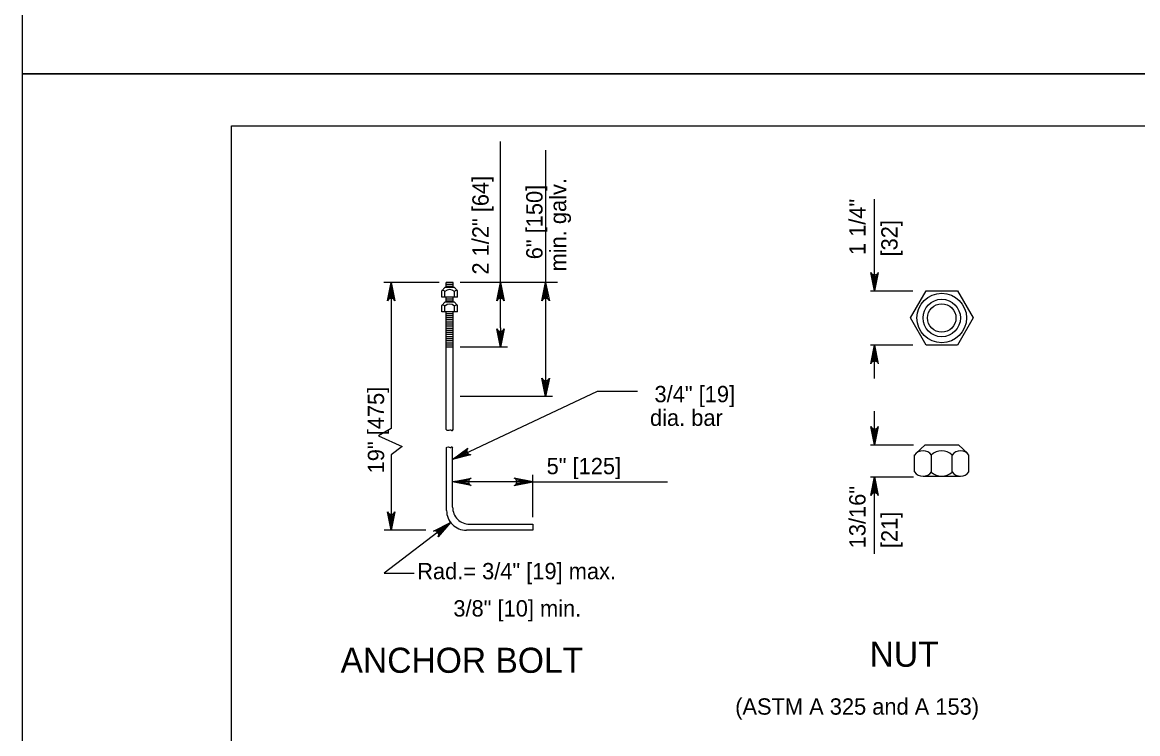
# Model space of a CAD drawing. Extents: x 1083.1 to 1117.1, y 675.4 to 741.4.
# Drawn here: x 1083.13 to 1093.79, y 691.05 to 697.84 of the extents above; entities that cross this region are included whole.
import ezdxf

# ---------------------------------------------------------------- set-up
doc = ezdxf.new("R2010")
doc.units = 0
doc.layers.add('Level 1', color=7, linetype='Continuous')

msp = doc.modelspace()

# ---------------------------------------------------------------- linework, layer by layer
at = {"layer": 'Level 1'}
for p, q in [((1117.126, 697.354), (1083.126, 697.354)), ((1083.126, 697.354), (1083.126, 675.354)), ((1087.696, 694.925), (1087.696, 696.707)), ((1088.127, 696.623), (1088.127, 694.268)), ((1091.272, 695.278), (1091.272, 696.156)), ((1091.249, 695.438), (1091.272, 695.278)), ((1091.26, 695.433), (1091.272, 695.278)), ((1091.296, 695.44), (1091.272, 695.278)), ((1091.286, 695.434), (1091.272, 695.278)), ((1091.272, 695.431), (1091.272, 695.278)), ((1087.109, 695.359), (1086.58, 695.359)), ((1086.628, 695.197), (1086.652, 695.359)), ((1086.638, 695.203), (1086.652, 695.359)), ((1086.652, 695.206), (1086.652, 695.359)), ((1086.664, 695.204), (1086.652, 695.359)), ((1086.675, 695.199), (1086.652, 695.359)), ((1086.652, 695.359), (1086.652, 693.963)), ((1087.135, 695.28), (1087.163, 695.31)), ((1087.257, 695.31), (1087.163, 695.31)), ((1087.176, 695.31), (1087.176, 695.359)), ((1087.245, 695.359), (1087.176, 695.359)), ((1087.245, 695.339), (1087.176, 695.339)), ((1087.245, 695.319), (1087.176, 695.319)), ((1087.245, 695.31), (1087.245, 695.359)), ((1087.285, 695.28), (1087.257, 695.31)), ((1088.24, 695.359), (1087.311, 695.359)), ((1087.671, 695.197), (1087.696, 695.359)), ((1087.682, 695.203), (1087.696, 695.359)), ((1087.696, 695.206), (1087.696, 695.359)), ((1087.708, 695.204), (1087.696, 695.359)), ((1087.719, 695.199), (1087.696, 695.359)), ((1088.102, 695.197), (1088.127, 695.359)), ((1088.113, 695.203), (1088.127, 695.359)), ((1088.127, 695.206), (1088.127, 695.359)), ((1088.139, 695.204), (1088.127, 695.359)), ((1088.15, 695.199), (1088.127, 695.359)), ((1087.135, 695.219), (1087.135, 695.28)), ((1087.285, 695.219), (1087.135, 695.219)), ((1087.164, 695.219), (1087.164, 695.273)), ((1087.176, 695.17), (1087.176, 695.219)), ((1087.245, 695.2), (1087.176, 695.2)), ((1087.245, 695.17), (1087.245, 695.219)), ((1087.256, 695.219), (1087.256, 695.273)), ((1087.285, 695.219), (1087.285, 695.28)), ((1091.232, 695.278), (1091.636, 695.278)), ((1091.613, 695.019), (1091.763, 695.278)), ((1091.763, 695.278), (1092.063, 695.278)), ((1092.063, 695.278), (1092.213, 695.019)), ((1087.135, 695.14), (1087.163, 695.17)), ((1087.135, 695.079), (1087.135, 695.14)), ((1087.257, 695.17), (1087.163, 695.17)), ((1087.164, 695.079), (1087.164, 695.133)), ((1087.245, 695.18), (1087.176, 695.18)), ((1087.256, 695.079), (1087.256, 695.133)), ((1087.285, 695.14), (1087.257, 695.17)), ((1087.285, 695.079), (1087.285, 695.14)), ((1087.285, 695.079), (1087.135, 695.079)), ((1087.244, 695.079), (1087.175, 695.079)), ((1087.176, 693.954), (1087.176, 695.079)), ((1087.245, 695.06), (1087.176, 695.06)), ((1087.245, 695.04), (1087.176, 695.04)), ((1087.245, 695.02), (1087.176, 695.02)), ((1087.245, 695), (1087.176, 695)), ((1087.245, 693.954), (1087.245, 695.079)), ((1091.763, 694.759), (1091.613, 695.019)), ((1092.213, 695.019), (1092.063, 694.759)), ((1087.245, 694.98), (1087.176, 694.98)), ((1087.245, 694.96), (1087.176, 694.96)), ((1087.245, 694.94), (1087.176, 694.94)), ((1087.245, 694.92), (1087.176, 694.92)), ((1087.245, 694.9), (1087.176, 694.9)), ((1087.245, 694.88), (1087.176, 694.88)), ((1087.674, 694.9), (1087.696, 694.74)), ((1087.685, 694.895), (1087.696, 694.74)), ((1087.696, 694.925), (1087.696, 694.74)), ((1087.721, 694.902), (1087.696, 694.74)), ((1087.711, 694.896), (1087.696, 694.74)), ((1087.696, 694.893), (1087.696, 694.74)), ((1087.245, 694.86), (1087.176, 694.86)), ((1087.245, 694.84), (1087.176, 694.84)), ((1087.245, 694.82), (1087.176, 694.82)), ((1087.245, 694.8), (1087.176, 694.8)), ((1087.245, 694.78), (1087.176, 694.78)), ((1087.245, 694.76), (1087.176, 694.76)), ((1087.245, 694.74), (1087.176, 694.74)), ((1087.763, 694.74), (1087.311, 694.74)), ((1091.636, 694.759), (1091.232, 694.759)), ((1091.247, 694.597), (1091.272, 694.759)), ((1091.257, 694.603), (1091.272, 694.759)), ((1091.272, 694.441), (1091.272, 694.759)), ((1091.272, 694.606), (1091.272, 694.759)), ((1091.283, 694.604), (1091.272, 694.759)), ((1091.294, 694.599), (1091.272, 694.759)), ((1092.063, 694.759), (1091.763, 694.759)), ((1088.105, 694.428), (1088.127, 694.268)), ((1088.116, 694.423), (1088.127, 694.268)), ((1088.152, 694.43), (1088.127, 694.268)), ((1088.142, 694.424), (1088.127, 694.268)), ((1088.127, 694.421), (1088.127, 694.268)), ((1088.194, 694.268), (1087.311, 694.268)), ((1091.272, 693.806), (1091.272, 694.129)), ((1091.249, 693.966), (1091.272, 693.806)), ((1091.26, 693.961), (1091.272, 693.806)), ((1091.296, 693.968), (1091.272, 693.806)), ((1091.286, 693.962), (1091.272, 693.806)), ((1091.272, 693.959), (1091.272, 693.806)), ((1086.652, 693.712), (1086.652, 692.99)), ((1087.181, 693.179), (1087.181, 693.781)), ((1087.239, 693.21), (1087.239, 693.782)), ((1087.374, 693.757), (1087.239, 693.668)), ((1087.374, 693.744), (1087.239, 693.668)), ((1087.377, 693.733), (1087.239, 693.668)), ((1087.386, 693.722), (1087.239, 693.668)), ((1087.396, 693.715), (1087.239, 693.668)), ((1091.232, 693.806), (1091.596, 693.806)), ((1091.596, 693.806), (1091.643, 693.806)), ((1091.654, 693.548), (1091.654, 693.71)), ((1091.666, 693.723), (1091.754, 693.806)), ((1091.754, 693.806), (1092.075, 693.806)), ((1091.814, 693.548), (1091.814, 693.71)), ((1092.013, 693.548), (1092.013, 693.71)), ((1092.161, 693.723), (1092.073, 693.806)), ((1092.173, 693.548), (1092.173, 693.71)), ((1088.005, 693.114), (1088.005, 693.519)), ((1091.232, 693.5), (1091.596, 693.5)), ((1091.247, 693.338), (1091.272, 693.5)), ((1091.257, 693.344), (1091.272, 693.5)), ((1091.272, 693.347), (1091.272, 693.5)), ((1091.283, 693.345), (1091.272, 693.5)), ((1091.294, 693.34), (1091.272, 693.5)), ((1091.272, 692.766), (1091.272, 693.5)), ((1091.596, 693.5), (1091.643, 693.5)), ((1091.734, 693.507), (1092.093, 693.507)), ((1087.399, 693.475), (1087.239, 693.453)), ((1087.394, 693.464), (1087.239, 693.453)), ((1087.917, 693.453), (1087.239, 693.453)), ((1087.392, 693.453), (1087.239, 693.453)), ((1087.395, 693.438), (1087.239, 693.453)), ((1087.401, 693.428), (1087.239, 693.453)), ((1087.843, 693.428), (1088.005, 693.453)), ((1087.845, 693.475), (1088.005, 693.453)), ((1087.849, 693.438), (1088.005, 693.453)), ((1087.85, 693.464), (1088.005, 693.453)), ((1087.852, 693.453), (1088.005, 693.453)), ((1088.005, 693.453), (1089.293, 693.453)), ((1086.63, 693.15), (1086.652, 692.99)), ((1086.641, 693.145), (1086.652, 692.99)), ((1086.677, 693.152), (1086.652, 692.99)), ((1086.667, 693.146), (1086.652, 692.99)), ((1086.652, 693.143), (1086.652, 692.99)), ((1087.076, 692.984), (1087.219, 693.064)), ((1087.087, 692.98), (1087.219, 693.064)), ((1087.098, 692.97), (1087.219, 693.064)), ((1087.103, 692.96), (1087.219, 693.064)), ((1087.106, 692.948), (1087.219, 693.064)), ((1086.984, 692.99), (1086.586, 692.99)), ((1088.005, 692.99), (1087.37, 692.99)), ((1087.401, 693.048), (1088.005, 693.048)), ((1088.005, 693.048), (1088.005, 692.99))]:
    msp.add_line(p, q, dxfattribs=at)
for points in [[(1083.126, 697.354), (1117.126, 697.354), (1117.126, 719.354), (1083.126, 719.354)], [(1083.126, 697.354), (1117.126, 697.354), (1117.126, 719.354), (1083.126, 719.354)], [(1085.126, 696.854), (1116.626, 696.854), (1116.626, 675.854), (1085.126, 675.854)]]:
    msp.add_lwpolyline(points, close=True, dxfattribs=at)
for points in [[(1091.307, 695.455), (1091.272, 695.278), (1091.236, 695.455)], [(1086.617, 695.182), (1086.652, 695.359), (1086.688, 695.182)], [(1087.661, 695.182), (1087.696, 695.359), (1087.732, 695.182)], [(1088.092, 695.182), (1088.127, 695.359), (1088.163, 695.182)], [(1087.732, 694.917), (1087.696, 694.74), (1087.661, 694.917)], [(1091.236, 694.582), (1091.272, 694.759), (1091.307, 694.582)], [(1088.163, 694.445), (1088.127, 694.268), (1088.092, 694.445)], [(1087.239, 693.668), (1088.623, 694.32), (1089.005, 694.32)], [(1086.652, 693.963), (1086.53, 693.894), (1086.758, 693.79), (1086.652, 693.712)], [(1091.307, 693.983), (1091.272, 693.806), (1091.236, 693.983)], [(1087.414, 693.712), (1087.239, 693.668), (1087.384, 693.776)], [(1087.416, 693.417), (1087.239, 693.453), (1087.416, 693.488)], [(1087.828, 693.417), (1088.005, 693.453), (1087.828, 693.488)], [(1091.236, 693.323), (1091.272, 693.5), (1091.307, 693.323)], [(1087.219, 693.064), (1086.585, 692.579), (1086.87, 692.579)], [(1086.688, 693.167), (1086.652, 692.99), (1086.617, 693.167)], [(1087.057, 692.983), (1087.219, 693.064), (1087.101, 692.928)]]:
    msp.add_lwpolyline(points, dxfattribs=at)
for centre, start, end in [((1091.272, 695.47), 202.0878, 337.9139), ((1086.652, 695.168), 22.0878, 157.9139), ((1087.696, 695.168), 22.0878, 157.9139), ((1088.127, 695.168), 22.0878, 157.9139), ((1087.696, 694.931), 202.0878, 337.9139), ((1091.272, 694.568), 22.0878, 157.9139), ((1088.127, 694.459), 202.0878, 337.9139), ((1091.272, 693.997), 202.0878, 337.9139), ((1087.412, 693.75), 137.3207, 273.1468), ((1087.43, 693.453), 112.0878, 247.9139), ((1087.814, 693.453), 292.0861, 67.9122), ((1091.272, 693.309), 22.0878, 157.9139), ((1086.652, 693.181), 202.0878, 337.9139), ((1087.068, 692.947), 329.8334, 105.6595)]:
    msp.add_arc(centre, 0.0382, start, end, dxfattribs=at)
for centre, major_axis, start_param, end_param in [((1087.142, 695.249), (0.0323, 0), 0.841371, 1.799879), ((1087.21, 695.222), (-0.0689, 0), 3.978969, 5.445809), ((1087.278, 695.249), (-0.0323, 0), 4.483307, 5.441815), ((1087.142, 695.109), (0.0323, 0), 0.841371, 1.799879), ((1087.21, 695.082), (-0.0689, 0), 3.978969, 5.445809), ((1087.278, 695.109), (-0.0323, 0), 4.483307, 5.441815), ((1091.734, 693.65), (0, 0.0996), 5.350865, 7.216249), ((1091.913, 693.606), (0, 0.144), 5.516191, 7.05018), ((1092.093, 693.65), (0, 0.0996), 5.350122, 7.215506), ((1091.734, 693.607), (0, -0.0996), 5.350122, 7.215506), ((1091.913, 693.651), (0, -0.144), 5.51734, 7.049031), ((1092.093, 693.607), (0, -0.0996), 5.350865, 7.216249), ((1087.37, 693.179), (0.189, 0), 3.141022, 4.71296), ((1087.401, 693.21), (0.162, 0), 3.140909, 4.713073)]:
    msp.add_ellipse(centre, major_axis=major_axis, ratio=0.999895, start_param=start_param, end_param=end_param, dxfattribs=at)
for major_axis in [(0, 0.237), (0, 0.179), (0, -0.136)]:
    msp.add_ellipse((1091.913, 695.019), major_axis=major_axis, ratio=0.999895, dxfattribs=at)
for points in [[(1087.176, 693.954), (1087.185, 693.948), (1087.206, 693.948), (1087.221, 693.95), (1087.229, 693.943), (1087.245, 693.954)], [(1087.181, 693.781), (1087.185, 693.784), (1087.206, 693.784), (1087.221, 693.782), (1087.229, 693.789), (1087.239, 693.782)]]:
    msp.add_spline(points, degree=3, dxfattribs=at)

# ---------------------------------------------------------------- texts
for s, p in [('2 1/2" [64]', (1087.583, 695.434)), ('6" [150]', (1088.098, 695.58)), ('min. galv.', (1088.324, 695.464)), ('1 1/4"', (1091.185, 695.62)), ('[32]', (1091.491, 695.607)), ('19" [475]', (1086.584, 693.534)), ('13/16"', (1091.185, 692.818)), ('[21]', (1091.491, 692.82))]:
    msp.add_text(s, height=0.156, rotation=90, dxfattribs=at).set_placement(p)
for s, height, p in [('3/4" [19]', 0.156, (1089.168, 694.214)), ('dia. bar', 0.156, (1089.125, 693.988)), ('5" [125]', 0.156, (1088.137, 693.526)), ('Rad.= 3/4" [19] max.', 0.156, (1086.9, 692.522)), ('      3/8" [10] min. ', 0.156, (1086.898, 692.166)), ('NUT', 0.24, (1091.224, 691.686)), ('ANCHOR BOLT', 0.24, (1086.168, 691.628)), ('(ASTM A 325 and A 153)', 0.156, (1089.939, 691.228))]:
    msp.add_text(s, height=height, dxfattribs=at).set_placement(p)

doc.saveas('drawing.dxf')
